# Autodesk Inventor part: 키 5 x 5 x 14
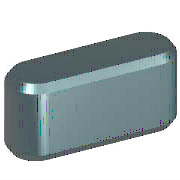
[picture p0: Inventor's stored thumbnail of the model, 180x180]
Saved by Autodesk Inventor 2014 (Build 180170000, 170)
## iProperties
IsCustomPart: 1
Created: 2012-02
Part Number: 키 5 x 5 x 14
Material: 강철, 연강
Description: 키 및 해당 키홈
Document SubType Name: Modeling
Standard: KS B 1311
Designer: mduedu
Standards Organization: KS
Language: ko-KR
Size Designation: 5 x 5 x 14
Categories: <MemberInstance><Categories><Category DisplayName="샤프트 부품" InternalName="7f7aeb1f-a693-4053-b835-cee3144e0d98" Mnemonic="SHFT"><Category DisplayName="키" Interna
Density: 1 g/cm^3
Appearance: 노란색
Author: mduedu
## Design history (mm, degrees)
workplane "Work Plane1"
workplane "Work Plane2"
sketch "스케치1"
  geometry: L1 (2.5, 2.5)-(11.5, 2.5); L2 (11.5, -2.5)-(2.5, -2.5); L3 (0, 9.4)-(0, -7.4) reference; L4 (-5, 0)-(30, 0) reference; L5 (14, 0)-(14, 7); A1 r 2.5 centre (2.5, 0) between (2.5, 2.5) and (2.5, -2.5); A2 r 2.5 centre (11.5, 0) between (11.5, -2.5) and (11.5, 2.5)
  constraints: 6 end point, 5 point on circle, 4 tangent, 3 point on line, 2 centre point, 1 horizontal, 1 parallel, 1 perpendicular
  dimensions: "d0" = 2.5 radius of A1 (= 0.5 x PB); "d13" = 2.5 radius of A2 (= 0.5 x PB); "d14" = 14 distance between parallel lines of L5 L3 (= NLG)
extrude "본체1" new body sketch "스케치1" taper "d3" = 0 deg; stored distance "d4" = 10
workplane "Work Plane3"
body "Solid1"
chamfer "모따기1" distance "d8" = 0.4 (= PHH); stored, may be unused: second distance "d9" = 0.4 (= PHH), angle "d15" = 45 deg
other parameters: "d1" = -3 (= -PNT), "d2" = 2 (= PH - PNT), "NLG" = 14 [user parameter; used in 3 equation terms], "PB" = 5 [user parameter; used in 2 equation terms], "PNT" = 3 [user parameter; used in 2 equation terms], "PH" = 5 [user parameter; used in 1 equation term], "PHH" = 0.4 [user parameter; used in 2 equation terms], "d10" = 0, "d16" = 0, "d17" = 0, "d18" = 0, "WDMIN" = 12 [user parameter], "PLB2" = 14 (= NLG) [user parameter], "WDMAX" = 17 [user parameter], "PLB1" = 14 (= NLG) [user parameter], "RR" = 0.16 [user parameter], "PUEB" = 2.3 [user parameter]
